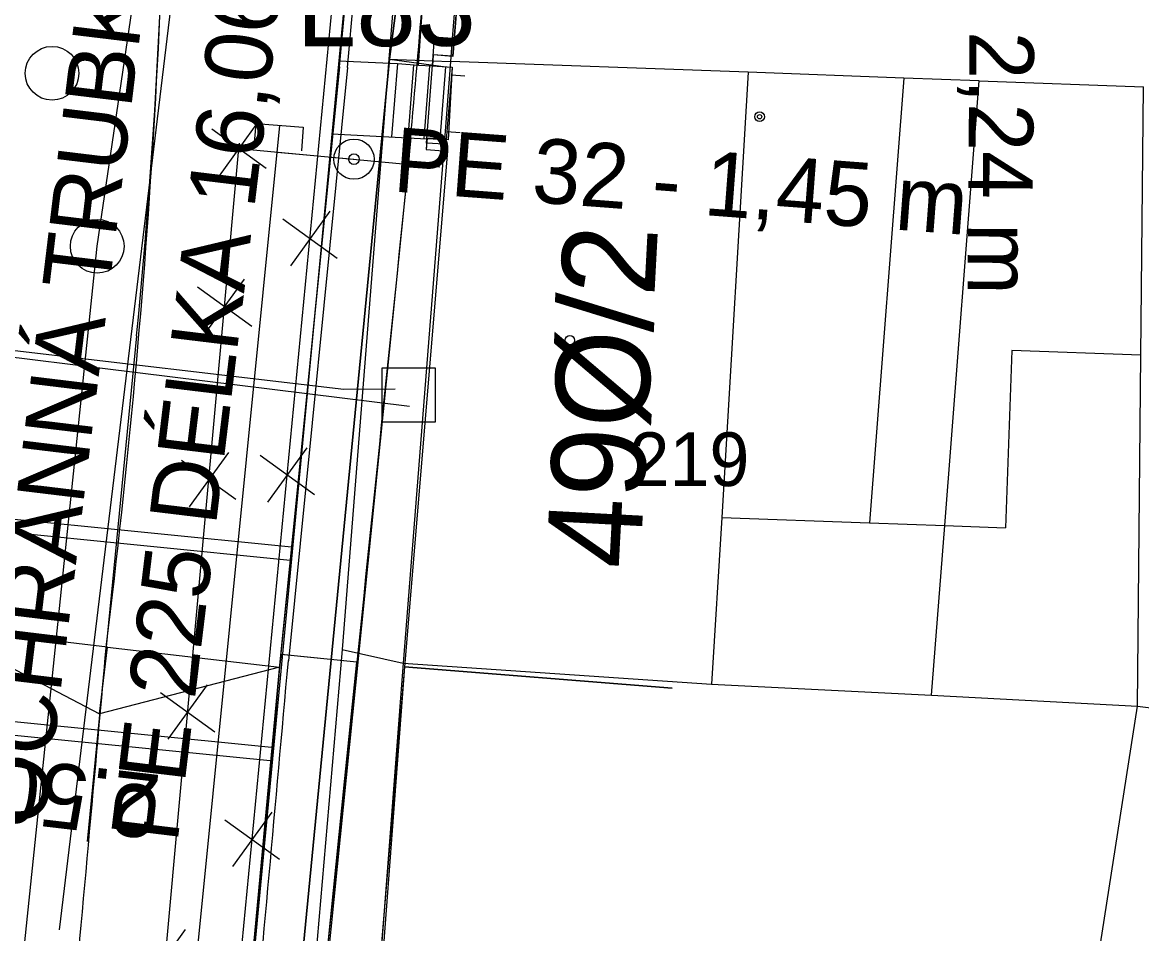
# Model space of a CAD drawing. Extents: x -643342 to -638635, y -1201752 to -1189948.
# Drawn here: x -639495.38 to -639474.55, y -1192753.31 to -1192736.34 of the extents above; entities that cross this region are included whole.
import ezdxf

# ---------------------------------------------------------------- set-up
doc = ezdxf.new("R2010")
doc.units = 0
for name, color, linetype in [('-zbytky_kruháče', 7, 'Continuous'), ('2', 7, 'Continuous'), ('42', 7, 'Continuous'), ('IS_PLYN_STL', 7, 'Continuous'), ('IS_TELEF_MISTNI_ZAMERENO', 7, 'Continuous'), ('IS_VODOVOD_PRIPOJKA DOMOVNÍ', 7, 'Continuous'), ('K-HRANICE_KN', 7, 'Continuous'), ('K-SLUCKOVE CARY', 7, 'Continuous'), ('K-ČÍSLA_PARCEL', 7, 'Continuous'), ('kanalizace_dešťová_stávající', 7, 'Continuous'), ('N-CHODNIK', 7, 'Continuous'), ('N-KAN_DEST_SACHTY-NÁVRH', 7, 'Continuous'), ('N-KAN_DEST_TRASA-NÁVRH', 7, 'Continuous'), ('N-OBVOD STAVBY 06', 7, 'Continuous'), ('N-OSA', 7, 'Continuous'), ('N-rusene_vedeni', 7, 'Continuous'), ('N-SILNICE', 7, 'Continuous'), ('N-SO101_KLOPENI', 7, 'Continuous'), ('N-SRAFY_PLOCHY', 7, 'Continuous'), ('RWE_STL_PRIPOJKY', 7, 'Continuous'), ('RWE_STL_RADY', 7, 'Continuous'), ('SN-PLYN-STL', 7, 'Continuous'), ('tomaštík - Džuganovi - Vrstva 36', 7, 'Continuous'), ('Vrstva 13', 7, 'Continuous'), ('Vrstva 46', 7, 'Continuous'), ('Z-budovy', 7, 'Continuous'), ('Z-hrany_a_čáry', 7, 'Continuous'), ('Z-popisy', 7, 'Continuous'), ('Z-vchody_vjezdy', 7, 'Continuous'), ('Z-značky', 7, 'Continuous'), ('Z-šachty_poklopy', 7, 'Continuous')]:
    doc.layers.add(name, color=color, linetype=linetype)

# ---------------------------------------------------------------- blocks, each defined once
blk = doc.blocks.new('SZASL')
at = {"layer": 'Vrstva 13'}
for p, q in [((-44.1, 44.1), (0, 44.1)), ((0, 44.1), (0, -44.1)), ((0, -44.1), (-44.1, -44.1))]:
    blk.add_line(p, q, dxfattribs=at)

msp = doc.modelspace()

# ---------------------------------------------------------------- linework, layer by layer
at = {"layer": '-zbytky_kruháče'}
msp.add_line((-639493.256, -1192742.179), (-639494.177, -1192751.593), dxfattribs=at)
msp.add_arc((-639614.395, -1192730.331), 121.717, 354.41408, 359.6946, dxfattribs=at)
at = {"layer": '2'}
msp.add_circle((-639489.209, -1192738.889), 0.375, dxfattribs=at)
at = {"layer": '42'}
msp.add_line((-639494.69, -1192753.239), (-639491.4, -1192726.011), dxfattribs=at)
at = {"layer": 'IS_PLYN_STL'}
for p, q in [((-639492.72, -1192753.74), (-639491.35, -1192738.69)), ((-639491.35, -1192738.69), (-639491.34, -1192738.59))]:
    msp.add_line(p, q, dxfattribs=at)
msp.add_lwpolyline([(-639491.35, -1192738.69), (-639488.36, -1192738.97), (-639487.61, -1192739.03)], dxfattribs=at)
at = {"layer": 'IS_TELEF_MISTNI_ZAMERENO'}
for p, q in [((-639487.92, -1192732.2), (-639488.55, -1192737.03)), ((-639488.55, -1192737.03), (-639487.92, -1192732.2)), ((-639488.55, -1192737.03), (-639490.59, -1192758.06)), ((-639490.59, -1192758.06), (-639488.55, -1192737.03)), ((-639488.55, -1192737.03), (-639487.5, -1192737.17))]:
    msp.add_line(p, q, dxfattribs=at)
at = {"layer": 'IS_VODOVOD_PRIPOJKA DOMOVNÍ'}
for points in [[(-639497.188, -1192742.573), (-639497.08, -1192742.58), (-639496.151, -1192742.644), (-639495.95, -1192742.4), (-639489.396, -1192743.168), (-639488.439, -1192743.166)], [(-639497.227, -1192743.11), (-639497.02, -1192743.12), (-639496.196, -1192743.161), (-639495.797, -1192742.541), (-639488.178, -1192743.486)]]:
    msp.add_lwpolyline(points, dxfattribs=at)
at = {"layer": 'K-HRANICE_KN'}
for p, q in [((-639488.23, -1192732.93), (-639488.56, -1192737.03)), ((-639488.56, -1192737.03), (-639489.43, -1192748.02)), ((-639488.56, -1192737.03), (-639487.74, -1192737.06)), ((-639487.74, -1192737.06), (-639487.41, -1192737.07)), ((-639481.87, -1192737.27), (-639487.41, -1192737.07)), ((-639478.97, -1192737.38), (-639481.87, -1192737.27)), ((-639477.57, -1192737.43), (-639478.97, -1192737.38)), ((-639478.21, -1192745.71), (-639477.57, -1192737.43)), ((-639474.56, -1192742.54), (-639474.51, -1192737.54)), ((-639474.62, -1192749.07), (-639474.56, -1192742.54)), ((-639478.46, -1192748.87), (-639478.21, -1192745.71)), ((-639489.43, -1192748.02), (-639490.57, -1192761.34)), ((-639489.43, -1192748.02), (-639488.29, -1192748.27)), ((-639488.29, -1192748.27), (-639482.55, -1192748.66)), ((-639482.55, -1192748.66), (-639478.46, -1192748.87)), ((-639478.46, -1192748.87), (-639474.62, -1192749.07)), ((-639474.62, -1192749.07), (-639470.47, -1192749.61))]:
    msp.add_line(p, q, dxfattribs=at)
at = {"layer": 'K-SLUCKOVE CARY'}
for p, q in [((-639487.02, -1192731.99), (-639487.38, -1192736.64)), ((-639487.74, -1192737.06), (-639487.71, -1192736.62)), ((-639487.38, -1192736.64), (-639487.71, -1192736.62)), ((-639487.38, -1192736.64), (-639487.41, -1192737.07)), ((-639487.86, -1192738.59), (-639487.74, -1192737.06)), ((-639487.41, -1192737.07), (-639487.53, -1192738.61)), ((-639481.87, -1192737.27), (-639482.36, -1192745.56)), ((-639478.97, -1192737.38), (-639479.61, -1192745.66)), ((-639477.57, -1192737.43), (-639474.51, -1192737.54)), ((-639487.53, -1192738.61), (-639488.29, -1192748.27)), ((-639487.53, -1192738.61), (-639487.86, -1192738.59)), ((-639476.96, -1192742.45), (-639477.08, -1192745.75)), ((-639474.56, -1192742.54), (-639476.96, -1192742.45)), ((-639482.36, -1192745.56), (-639482.55, -1192748.66)), ((-639482.36, -1192745.56), (-639479.61, -1192745.66)), ((-639479.61, -1192745.66), (-639478.21, -1192745.71)), ((-639478.21, -1192745.71), (-639477.08, -1192745.75)), ((-639488.29, -1192748.27), (-639488.79, -1192754.73)), ((-639475.47, -1192754.52), (-639474.62, -1192749.07))]:
    msp.add_line(p, q, dxfattribs=at)
at = {"layer": 'K-ČÍSLA_PARCEL'}
msp.add_circle((-639485.19, -1192742.259), 0.0875, dxfattribs=at)
at = {"layer": 'kanalizace_dešťová_stávající'}
msp.add_lwpolyline([(-639500.838, -1192858.606), (-639498.4, -1192827.95), (-639495.47, -1192797.17), (-639492.53, -1192766.39), (-639489.24, -1192732.18), (-639488.56, -1192730.68), (-639487.73, -1192718.33)], dxfattribs=at)
at = {"layer": 'N-CHODNIK'}
for p, q in [((-639497.001, -1192745.444), (-639490.369, -1192746.106)), ((-639497.008, -1192745.694), (-639490.394, -1192746.355)), ((-639497.193, -1192749.193), (-639490.742, -1192749.837)), ((-639497.211, -1192749.443), (-639490.767, -1192750.086))]:
    msp.add_line(p, q, dxfattribs=at)
at = {"layer": 'N-KAN_DEST_SACHTY-NÁVRH'}
msp.add_circle((-639493.988, -1192740.511), 0.5, dxfattribs=at)
at = {"layer": 'N-KAN_DEST_TRASA-NÁVRH'}
msp.add_lwpolyline([(-639498.884, -1192834.039), (-639503.116, -1192829.951), (-639498.124, -1192780.201), (-639493.988, -1192740.511), (-639490.998, -1192720.223)], dxfattribs=at)
at = {"layer": 'N-OBVOD STAVBY 06'}
msp.add_lwpolyline([(-639474.45, -1192730.22), (-639477.09, -1192730.07), (-639479.659, -1192729.992), (-639480.358, -1192729.971), (-639481.055, -1192729.95), (-639481.055, -1192729.95), (-639481.055, -1192729.95), (-639483.73, -1192729.869), (-639485.02, -1192729.83), (-639486.05, -1192730.57), (-639486.505, -1192731.986), (-639486.97, -1192731.97), (-639487.377, -1192736.974), (-639487.736, -1192736.945), (-639487.747, -1192737.154), (-639487.383, -1192737.174), (-639487.455, -1192738.531), (-639487.849, -1192738.499), (-639487.866, -1192738.709), (-639487.47, -1192738.74), (-639488.76, -1192754.221)], dxfattribs=at)
at = {"layer": 'N-OSA'}
for centre, radius, start, end in [((-639643.94, -1192729.259), 151.279, 352.91287, 0.41512), ((-642481.96, -1192481.467), 3000, 354.75156, 354.904349)]:
    msp.add_arc(centre, radius, start, end, dxfattribs=at)
at = {"layer": 'N-rusene_vedeni'}
for p, q in [((-639491.857, -1192738.324), (-639490.843, -1192739.056)), ((-639490.984, -1192738.183), (-639491.716, -1192739.197)), ((-639490.534, -1192739.999), (-639489.52, -1192740.731)), ((-639489.661, -1192739.859), (-639490.393, -1192740.872)), ((-639491.252, -1192741.122), (-639491.983, -1192742.135)), ((-639492.124, -1192741.263), (-639491.111, -1192741.995)), ((-639491.545, -1192744.349), (-639492.277, -1192745.362)), ((-639490.085, -1192744.261), (-639490.816, -1192745.275)), ((-639492.418, -1192744.49), (-639491.405, -1192745.221)), ((-639490.957, -1192744.402), (-639489.944, -1192745.134)), ((-639491.939, -1192748.676), (-639492.671, -1192749.689)), ((-639492.812, -1192748.817), (-639491.798, -1192749.548)), ((-639490.737, -1192751.047), (-639491.469, -1192752.06)), ((-639491.61, -1192751.188), (-639490.596, -1192751.919)), ((-639492.354, -1192753.233), (-639493.086, -1192754.247))]:
    msp.add_line(p, q, dxfattribs=at)
at = {"layer": 'N-SILNICE'}
for p, q in [((-639489.477, -1192737.167), (-639489.142, -1192733.365)), ((-639489.328, -1192737.18), (-639488.993, -1192733.378)), ((-639489.477, -1192737.167), (-639490.58, -1192748.212)), ((-639489.328, -1192737.182), (-639490.43, -1192748.227)), ((-639489.154, -1192748.252), (-639490.57, -1192748.11))]:
    msp.add_line(p, q, dxfattribs=at)
for centre, radius, start, end in [((-639703.47, -1192718.615), 216.232, 354.61868, 356.11148), ((-627942.694, -1193936.453), 11607.436, 174.0781645, 174.1903436), ((-642481.96, -1192481.467), 3003.25, 354.75156, 354.904349), ((-642481.96, -1192481.467), 3003.4, 354.75156, 354.904349)]:
    msp.add_arc(centre, radius, start, end, dxfattribs=at)
at = {"layer": 'N-SO101_KLOPENI'}
for points in [[(-639493.797, -1192747.973), (-639497.052, -1192747.591), (-639493.944, -1192749.215), (-639493.797, -1192747.973)], [(-639493.797, -1192747.973), (-639490.594, -1192748.346), (-639493.944, -1192749.215), (-639493.797, -1192747.973)], [(-639493.797, -1192747.973), (-639490.594, -1192748.346), (-639493.944, -1192749.215), (-639493.797, -1192747.973)]]:
    msp.add_lwpolyline(points, close=True, dxfattribs=at)
at = {"layer": 'N-SRAFY_PLOCHY'}
for p, q in [((-639489.792, -1192740.358), (-639489.354, -1192735.806)), ((-639490.162, -1192744.068), (-639489.792, -1192740.358)), ((-639490.58, -1192748.25), (-639490.162, -1192744.068)), ((-639492.401, -1192767.763), (-639490.58, -1192748.25))]:
    msp.add_line(p, q, dxfattribs=at)
msp.add_lwpolyline([(-639489.698, -1192753.548), (-639489.377, -1192750.419), (-639489.154, -1192748.252), (-639490.565, -1192748.111), (-639490.594, -1192748.346), (-639490.734, -1192749.933), (-639490.809, -1192750.775), (-639491.02, -1192753.104), (-639491.228, -1192755.364)], dxfattribs=at)
at = {"layer": 'RWE_STL_PRIPOJKY'}
msp.add_line((-639490.641, -1192738.756), (-639489.209, -1192738.889), dxfattribs=at)
at = {"layer": 'RWE_STL_RADY'}
msp.add_lwpolyline([(-639497.844, -1192828.492), (-639491.5, -1192762.757), (-639493.022, -1192762.61), (-639492.143, -1192753.805), (-639490.591, -1192738.259)], dxfattribs=at)
at = {"layer": 'SN-PLYN-STL'}
msp.add_circle((-639489.209, -1192738.889), 0.1, dxfattribs=at)
at = {"layer": 'Z-budovy'}
for p, q in [((-639486.97, -1192731.97), (-639487.367, -1192736.975)), ((-639487.736, -1192736.945), (-639487.753, -1192737.154)), ((-639487.367, -1192736.975), (-639487.736, -1192736.945)), ((-639487.753, -1192737.154), (-639487.383, -1192737.174)), ((-639487.383, -1192737.174), (-639487.395, -1192737.324)), ((-639487.395, -1192737.324), (-639487.479, -1192738.379)), ((-639487.85, -1192738.51), (-639487.866, -1192738.709)), ((-639487.491, -1192738.529), (-639487.85, -1192738.51)), ((-639487.479, -1192738.379), (-639487.491, -1192738.529)), ((-639487.47, -1192738.74), (-639488.27, -1192748.34)), ((-639487.866, -1192738.709), (-639487.47, -1192738.74)), ((-639488.27, -1192748.34), (-639488.756, -1192754.79)), ((-639483.286, -1192748.736), (-639488.27, -1192748.34)), ((-639488.27, -1192748.34), (-639483.286, -1192748.736))]:
    msp.add_line(p, q, dxfattribs=at)
at = {"layer": 'Z-hrany_a_čáry'}
for p, q in [((-639488.01, -1192737.14), (-639487.68, -1192732.5)), ((-639489.09, -1192732.86), (-639491.44, -1192757.6)), ((-639489.49, -1192737.06), (-639488.4, -1192737.11)), ((-639488.4, -1192737.11), (-639488.509, -1192738.475)), ((-639488.4, -1192737.11), (-639488.01, -1192737.14)), ((-639488.101, -1192737.133), (-639488.209, -1192738.491)), ((-639488.01, -1192737.14), (-639487.753, -1192737.154)), ((-639487.801, -1192737.151), (-639487.91, -1192738.507)), ((-639487.502, -1192737.168), (-639487.61, -1192738.523)), ((-639491.75, -1192774.21), (-639488.147, -1192738.494)), ((-639489.618, -1192738.415), (-639487.85, -1192738.51))]:
    msp.add_line(p, q, dxfattribs=at)
at = {"layer": 'Z-vchody_vjezdy'}
for p, q in [((-639487.395, -1192737.324), (-639487.479, -1192738.379)), ((-639487.146, -1192737.344), (-639487.395, -1192737.324)), ((-639487.23, -1192738.399), (-639487.479, -1192738.379))]:
    msp.add_line(p, q, dxfattribs=at)
at = {"layer": 'Z-značky'}
for radius in [0.09, 0.0398]:
    msp.add_circle((-639481.658, -1192738.099), radius, dxfattribs=at)
at = {"layer": 'Z-šachty_poklopy'}
for p, q in [((-639487.69, -1192742.78), (-639488.69, -1192742.78)), ((-639488.69, -1192742.78), (-639488.69, -1192743.78)), ((-639487.69, -1192743.78), (-639487.69, -1192742.78)), ((-639488.69, -1192743.78), (-639487.69, -1192743.78))]:
    msp.add_line(p, q, dxfattribs=at)
msp.add_circle((-639494.83, -1192737.29), 0.5, dxfattribs=at)

# ---------------------------------------------------------------- block references
at = {"layer": 'RWE_STL_RADY', "xscale": 0.01, "yscale": 0.009999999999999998, "rotation": 85.27319882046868}
msp.add_blockref('SZASL', (-639490.591, -1192738.259), dxfattribs=at)

# ---------------------------------------------------------------- texts
at = {"layer": 'K-ČÍSLA_PARCEL'}
msp.add_text('49%%c/2', height=1.75, rotation=86.9721, dxfattribs=at).set_placement((-639483.886, -1192746.532))
at = {"layer": 'N-SO101_KLOPENI'}
msp.add_text('2.50%', height=1.2, rotation=173.3259, dxfattribs=at).set_placement((-639492.774, -1192750.362))
at = {"layer": 'RWE_STL_RADY'}
for s, rotation, p in [('PE 32 - 2,24 m', 269.5644, (-639477.706, -1192730.708)), ('PE 32 - 1,45 m', 355.6623, (-639488.499, -1192739.489))]:
    msp.add_text(s, height=1.2, rotation=rotation, dxfattribs=at).set_placement(p)
at = {"layer": 'tomaštík - Džuganovi - Vrstva 36'}
for s, p in [('PE 225 DÉLKA 16,06 m', (-639492.496, -1192751.636)), ('OCHRANNÁ TRUBKA ', (-639494.978, -1192751.335))]:
    msp.add_text(s, height=1.25, rotation=83.0956, dxfattribs=at).set_placement(p)
at = {"layer": 'Vrstva 46'}
msp.add_text('L83', height=1.5, rotation=0.301, dxfattribs=at).set_placement((-639490.282, -1192736.791))
at = {"layer": 'Z-popisy'}
msp.add_text('219', height=1, dxfattribs=at).set_placement((-639484.079, -1192744.975))

doc.saveas('drawing.dxf')
